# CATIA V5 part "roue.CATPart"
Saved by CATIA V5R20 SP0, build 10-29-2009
Part number: roue
Bounding box of the stored display mesh (mm): x -100 to 100, y -100 to 100, z 0 to 10
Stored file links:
  D:\Dropbox\IAO_2011\MMS_GR1\jdubreuilr\jdubreuilr\jdubreuilr\roue.CATPart
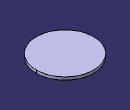
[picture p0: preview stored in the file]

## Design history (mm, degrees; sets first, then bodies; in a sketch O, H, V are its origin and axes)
Set1
  Point1: (0, 0, 0)
  Line1: type Normal, RefPoint Point1, RefSkin end face of Pad1, Start 0, End 20
Body1 (main body)
  Sketch1 on xy-plane, origin (0, 0, 0), H (1, 0, 0), V (0, 1, 0)
    circle A1 centre (0, 0) radius 100
    radius A1 = 100
  Pad1: profile Sketch1, direction (0, 0, 1), length 10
